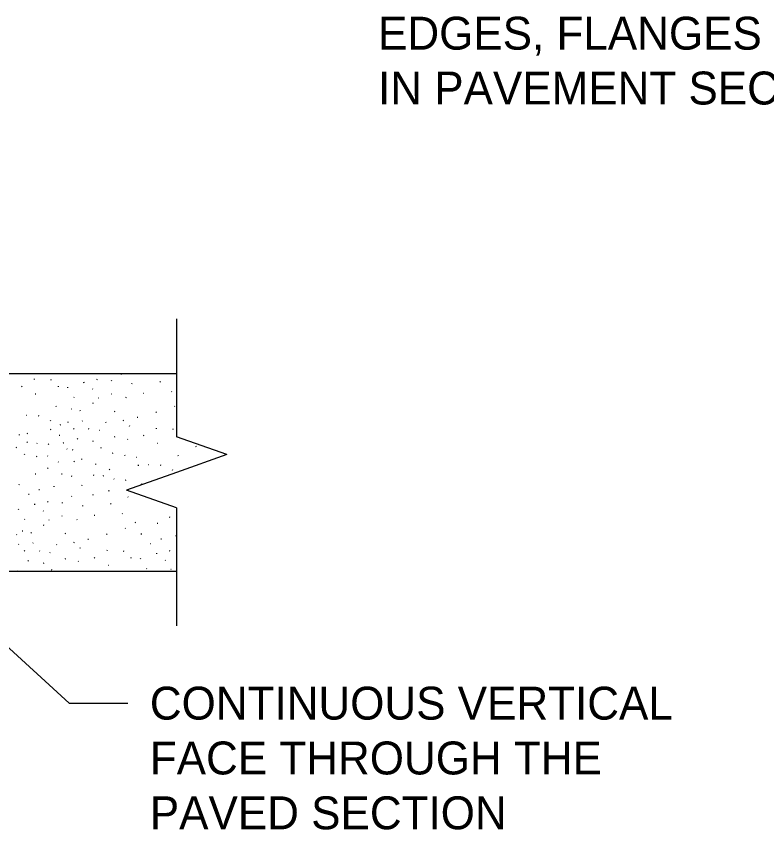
# Model space of a CAD drawing. Extents: x 49991.4 to 50029.7, y 49987.6 to 50011.4.
# Drawn here: x 50024.639 to 50026.008, y 49992.7 to 49994.183 of the extents above; entities that cross this region are included whole.
import ezdxf

# ---------------------------------------------------------------- set-up
doc = ezdxf.new("R2010")
doc.units = 0
for name, color, linetype in [('Level 1', 7, 'Continuous'), ('Level 2', 7, 'Continuous'), ('Level 3', 7, 'Continuous'), ('Level 6', 7, 'Continuous'), ('Level 9', 7, 'Continuous')]:
    doc.layers.add(name, color=color, linetype=linetype)

msp = doc.modelspace()

# ---------------------------------------------------------------- linework, layer by layer
at = {"layer": 'Level 1'}
for p, q in [((50024.5713, 49993.5314), (50024.9313, 49993.5314)), ((50024.5713, 49993.1714), (50024.9313, 49993.1714))]:
    msp.add_line(p, q, dxfattribs=at)
at = {"layer": 'Level 3'}
for p, q in [((50024.5713, 49993.0805), (50024.7354, 49992.9305)), ((50024.7354, 49992.9305), (50024.8425, 49992.9305))]:
    msp.add_line(p, q, dxfattribs=at)
at = {"layer": 'Level 6'}
for p, q in [((50024.9313, 49993.6314), (50024.9313, 49993.4162)), ((50025.0227, 49993.3838), (50024.9313, 49993.4162)), ((50025.0227, 49993.3838), (50024.9313, 49993.3514)), ((50024.9313, 49993.3514), (50024.8399, 49993.319)), ((50024.9313, 49993.2866), (50024.8399, 49993.319)), ((50024.9313, 49993.2866), (50024.9313, 49993.0714))]:
    msp.add_line(p, q, dxfattribs=at)
at = {"layer": 'Level 9'}
for p, q in [((50024.6717, 49993.5219), (50024.6715, 49993.5206)), ((50024.7031, 49993.5192), (50024.7021, 49993.52)), ((50024.7869, 49993.5198), (50024.7859, 49993.5207)), ((50024.8124, 49993.5191), (50024.8122, 49993.5178)), ((50024.8302, 49993.5303), (50024.8294, 49993.53)), ((50024.6496, 49993.5076), (50024.6486, 49993.5084)), ((50024.7152, 49993.5088), (50024.715, 49993.5075)), ((50024.7326, 49993.5068), (50024.7324, 49993.5055)), ((50024.7618, 49993.5163), (50024.7619, 49993.5149)), ((50024.8496, 49993.5135), (50024.8493, 49993.5122)), ((50024.9018, 49993.516), (50024.9008, 49993.5169)), ((50024.6744, 49993.4941), (50024.6736, 49993.4938)), ((50024.7787, 49993.5031), (50024.7777, 49993.5039)), ((50024.8125, 49993.4942), (50024.8117, 49993.4938)), ((50024.8718, 49993.4953), (50024.871, 49993.495)), ((50024.9226, 49993.4986), (50024.9218, 49993.4983)), ((50024.7444, 49993.4883), (50024.7436, 49993.4879)), ((50024.7796, 49993.477), (50024.7786, 49993.4778)), ((50024.7889, 49993.4868), (50024.7881, 49993.4864)), ((50024.84, 49993.4871), (50024.839, 49993.4879)), ((50024.7124, 49993.4709), (50024.7114, 49993.4718)), ((50024.7405, 49993.4669), (50024.7397, 49993.4666)), ((50024.7563, 49993.4632), (50024.7553, 49993.464)), ((50024.8184, 49993.4623), (50024.8176, 49993.462)), ((50024.8945, 49993.4607), (50024.8935, 49993.4615)), ((50024.9283, 49993.4715), (50024.9273, 49993.4723)), ((50024.6577, 49993.4552), (50024.6569, 49993.4549)), ((50024.6804, 49993.4537), (50024.6794, 49993.4546)), ((50024.7012, 49993.4461), (50024.7009, 49993.4448)), ((50024.7596, 49993.4453), (50024.7588, 49993.445)), ((50024.835, 49993.4452), (50024.834, 49993.446)), ((50024.8604, 49993.4516), (50024.8596, 49993.4513)), ((50024.7193, 49993.4378), (50024.7184, 49993.4374)), ((50024.7334, 49993.4428), (50024.7326, 49993.4425)), ((50024.7443, 49993.4304), (50024.7433, 49993.4313)), ((50024.7719, 49993.4299), (50024.7709, 49993.4308)), ((50024.803, 49993.4418), (50024.802, 49993.4427)), ((50024.8452, 49993.4362), (50024.845, 49993.4349)), ((50024.8943, 49993.432), (50024.894, 49993.4307)), ((50024.9256, 49993.4293), (50024.9246, 49993.4301)), ((50024.6444, 49993.4203), (50024.6442, 49993.419)), ((50024.6597, 49993.4216), (50024.6587, 49993.4224)), ((50024.7017, 49993.4293), (50024.7009, 49993.429)), ((50024.7183, 49993.4186), (50024.7174, 49993.4183)), ((50024.7907, 49993.4277), (50024.7899, 49993.4274)), ((50024.8184, 49993.4159), (50024.8176, 49993.4155)), ((50024.8721, 49993.4177), (50024.8711, 49993.4185)), ((50024.6592, 49993.406), (50024.6582, 49993.4069)), ((50024.6769, 49993.4043), (50024.6761, 49993.4039)), ((50024.6982, 49993.4022), (50024.6972, 49993.4031)), ((50024.7247, 49993.4047), (50024.7252, 49993.405)), ((50024.7252, 49993.405), (50024.7255, 49993.4052)), ((50024.7509, 49993.412), (50024.7499, 49993.4129)), ((50024.779, 49993.408), (50024.7781, 49993.4077)), ((50024.8425, 49993.4118), (50024.8416, 49993.4115)), ((50024.897, 49993.4042), (50024.8962, 49993.4039)), ((50024.6399, 49993.3959), (50024.6389, 49993.3967)), ((50024.732, 49993.3936), (50024.731, 49993.3944)), ((50024.7425, 49993.3918), (50024.7415, 49993.3927)), ((50024.7942, 49993.3952), (50024.7932, 49993.3961)), ((50024.8148, 49993.3864), (50024.814, 49993.386)), ((50024.9669, 49993.3984), (50024.9661, 49993.398)), ((50024.6538, 49993.3845), (50024.6535, 49993.3832)), ((50024.6767, 49993.3795), (50024.6757, 49993.3804)), ((50024.6966, 49993.3809), (50024.6956, 49993.3817)), ((50024.7161, 49993.3699), (50024.7151, 49993.3707)), ((50024.7449, 49993.3708), (50024.7439, 49993.3716)), ((50024.7579, 49993.3763), (50024.7576, 49993.375)), ((50024.8365, 49993.3836), (50024.8366, 49993.3823)), ((50024.8588, 49993.3787), (50024.8579, 49993.3784)), ((50024.9349, 49993.381), (50024.9339, 49993.3819)), ((50024.6971, 49993.3587), (50024.6961, 49993.3596)), ((50024.7836, 49993.3672), (50024.7834, 49993.3659)), ((50024.8094, 49993.356), (50024.8084, 49993.3569)), ((50024.8612, 49993.3649), (50024.8614, 49993.3635)), ((50024.8802, 49993.3653), (50024.8794, 49993.365)), ((50024.9029, 49993.3638), (50024.9019, 49993.3647)), ((50024.9237, 49993.3562), (50024.9235, 49993.3549)), ((50024.6743, 49993.3482), (50024.6735, 49993.3479)), ((50024.7223, 49993.3483), (50024.7215, 49993.348)), ((50024.7408, 49993.3436), (50024.7398, 49993.3444)), ((50024.781, 49993.3455), (50024.78, 49993.3464)), ((50024.7978, 49993.3448), (50024.797, 49993.3444)), ((50024.644, 49993.3295), (50024.6438, 49993.3282)), ((50024.7076, 49993.3264), (50024.7074, 49993.3251)), ((50024.7583, 49993.3279), (50024.7581, 49993.3266)), ((50024.8177, 49993.3389), (50024.8167, 49993.3397)), ((50024.8386, 49993.3371), (50024.8377, 49993.3368)), ((50024.867, 49993.3304), (50024.8667, 49993.3291)), ((50024.681, 49993.3197), (50024.6802, 49993.3194)), ((50024.8075, 49993.318), (50024.8073, 49993.3167)), ((50024.6621, 49993.3112), (50024.6613, 49993.3109)), ((50024.697, 49993.2973), (50024.696, 49993.2981)), ((50024.7225, 49993.2965), (50024.7223, 49993.2952)), ((50024.7403, 49993.3078), (50024.7395, 49993.3074)), ((50024.7797, 49993.3097), (50024.7787, 49993.3106)), ((50024.8432, 49993.306), (50024.8422, 49993.3068)), ((50024.6427, 49993.2842), (50024.6424, 49993.2829)), ((50024.6719, 49993.2938), (50024.672, 49993.2924)), ((50024.7596, 49993.2909), (50024.7594, 49993.2896)), ((50024.8119, 49993.2935), (50024.8109, 49993.2944)), ((50024.6888, 49993.2806), (50024.6878, 49993.2814)), ((50024.7226, 49993.2717), (50024.7218, 49993.2713)), ((50024.7819, 49993.2728), (50024.7811, 49993.2724)), ((50024.8327, 49993.2761), (50024.8319, 49993.2758)), ((50024.9196, 49993.2688), (50024.9186, 49993.2697)), ((50024.6545, 49993.2658), (50024.6537, 49993.2654)), ((50024.6897, 49993.2544), (50024.6887, 49993.2553)), ((50024.699, 49993.2643), (50024.6982, 49993.2639)), ((50024.7501, 49993.2645), (50024.7491, 49993.2654)), ((50024.8568, 49993.2591), (50024.8558, 49993.2599)), ((50024.8969, 49993.2583), (50024.896, 49993.258)), ((50024.6401, 49993.2373), (50024.6391, 49993.2382)), ((50024.6506, 49993.2444), (50024.6497, 49993.2441)), ((50024.6664, 49993.2407), (50024.6654, 49993.2415)), ((50024.7285, 49993.2398), (50024.7277, 49993.2394)), ((50024.8046, 49993.2382), (50024.8036, 49993.239)), ((50024.8384, 49993.249), (50024.8374, 49993.2498)), ((50024.8666, 49993.2396), (50024.8664, 49993.2383)), ((50024.6697, 49993.2228), (50024.6689, 49993.2224)), ((50024.7451, 49993.2227), (50024.7441, 49993.2235)), ((50024.7705, 49993.2291), (50024.7697, 49993.2288)), ((50024.9035, 49993.2298), (50024.9027, 49993.2295)), ((50024.9302, 49993.2365), (50024.9299, 49993.2352)), ((50024.6435, 49993.2203), (50024.6427, 49993.22)), ((50024.6544, 49993.2079), (50024.6534, 49993.2087)), ((50024.682, 49993.2074), (50024.681, 49993.2082)), ((50024.7131, 49993.2193), (50024.7121, 49993.2201)), ((50024.7553, 49993.2136), (50024.7551, 49993.2123)), ((50024.8044, 49993.2095), (50024.8041, 49993.2082)), ((50024.8357, 49993.2068), (50024.8347, 49993.2076)), ((50024.8846, 49993.2213), (50024.8838, 49993.221)), ((50024.9196, 49993.2074), (50024.9186, 49993.2082)), ((50024.7008, 49993.2052), (50024.7, 49993.2049)), ((50024.7285, 49993.1934), (50024.7277, 49993.193)), ((50024.7822, 49993.1951), (50024.7812, 49993.196)), ((50024.8478, 49993.1963), (50024.8476, 49993.195)), ((50024.8652, 49993.1943), (50024.865, 49993.193)), ((50024.8944, 49993.2039), (50024.8945, 49993.2025)), ((50024.661, 49993.1895), (50024.66, 49993.1904)), ((50024.689, 49993.1855), (50024.6882, 49993.1851)), ((50024.7526, 49993.1893), (50024.7517, 49993.189)), ((50024.8071, 49993.1817), (50024.8063, 49993.1814)), ((50024.9113, 49993.1907), (50024.9103, 49993.1915)), ((50024.6417, 49993.1714), (50024.6411, 49993.1719)), ((50024.7043, 49993.1727), (50024.7033, 49993.1735)), ((50024.877, 49993.1759), (50024.8762, 49993.1755)), ((50024.9215, 49993.1744), (50024.9207, 49993.174))]:
    msp.add_line(p, q, dxfattribs=at)

# ---------------------------------------------------------------- texts
at = {"layer": 'Level 2'}
for s, p in [('EDGES, FLANGES OR LIPS ', (50025.2988, 49994.1222)), ('IN PAVEMENT SECTION', (50025.2988, 49994.0222)), ('CONTINUOUS VERTICAL ', (50024.8825, 49992.9005)), ('FACE THROUGH THE ', (50024.8825, 49992.8005)), ('PAVED SECTION', (50024.8825, 49992.7005))]:
    msp.add_text(s, height=0.06, dxfattribs=at).set_placement(p)

doc.saveas('drawing.dxf')
